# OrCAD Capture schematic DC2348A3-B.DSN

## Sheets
1 PAGE2: size B; title: HIGH POWER POLY-PHASE; rev: 3; company: TM; note: BI-DIRECTIONAL SUPPLY/CHARGER
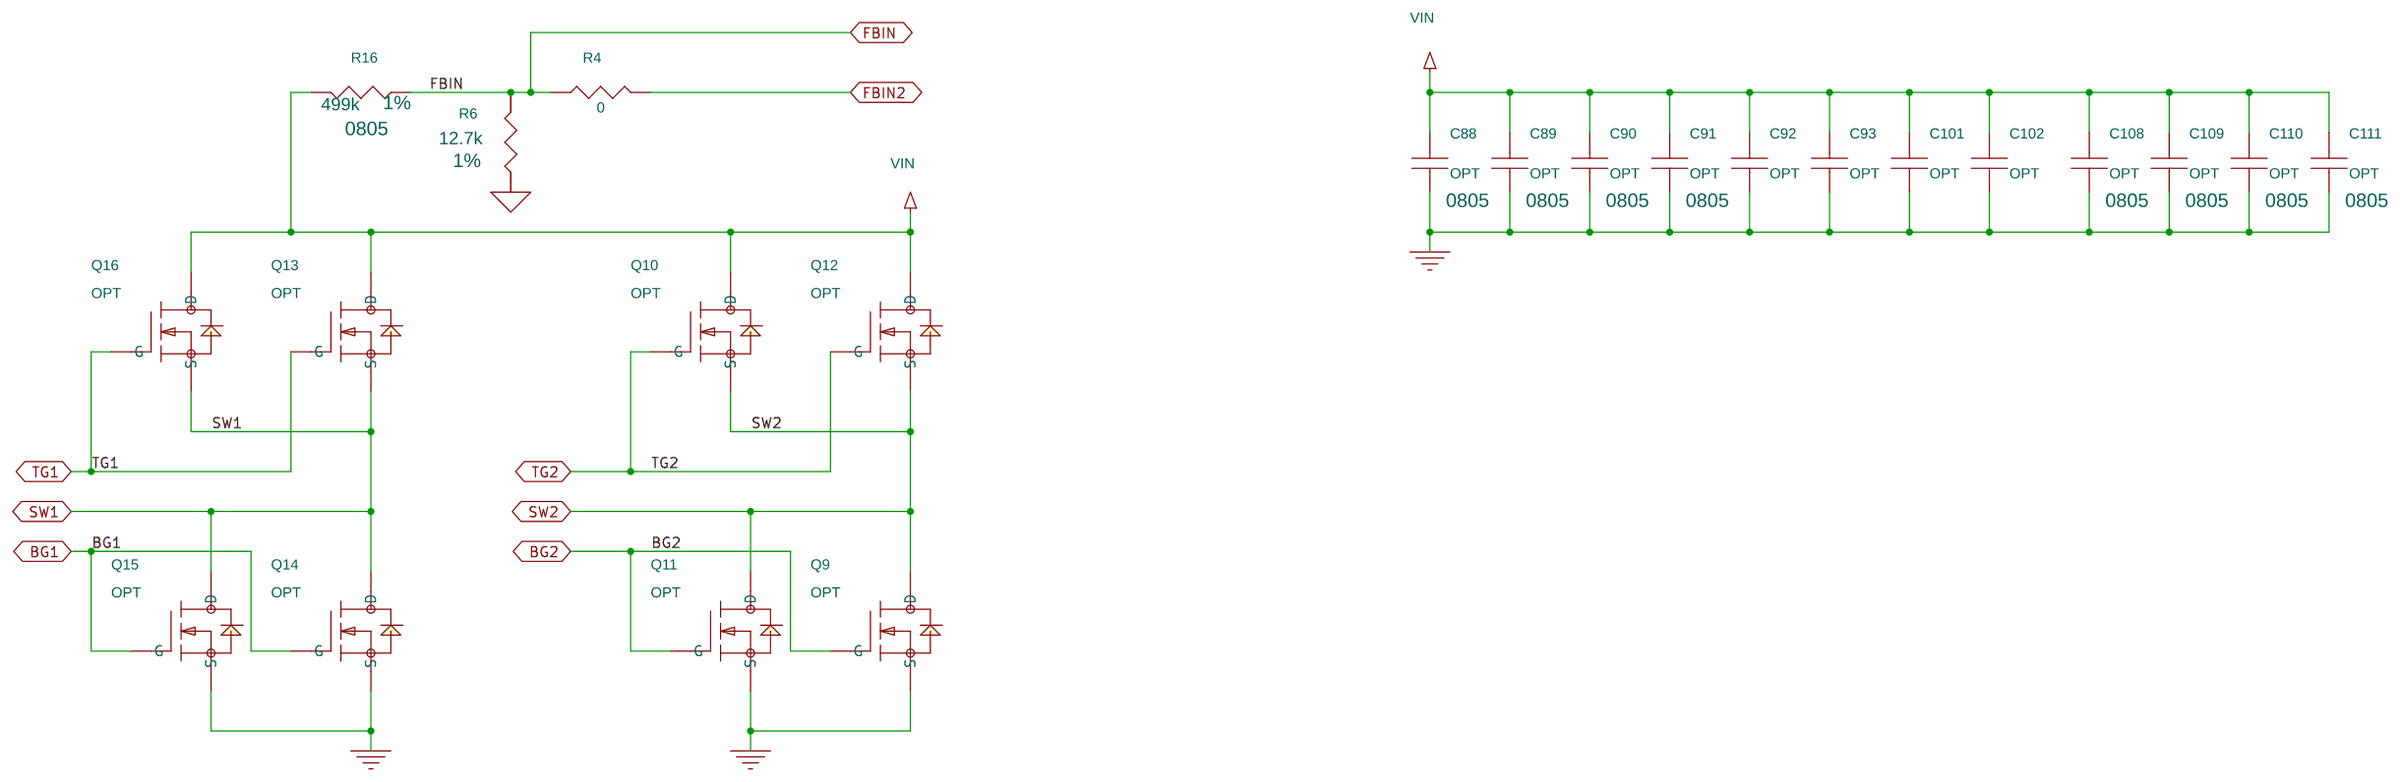
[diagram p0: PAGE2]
2 PAGE1: size Custom
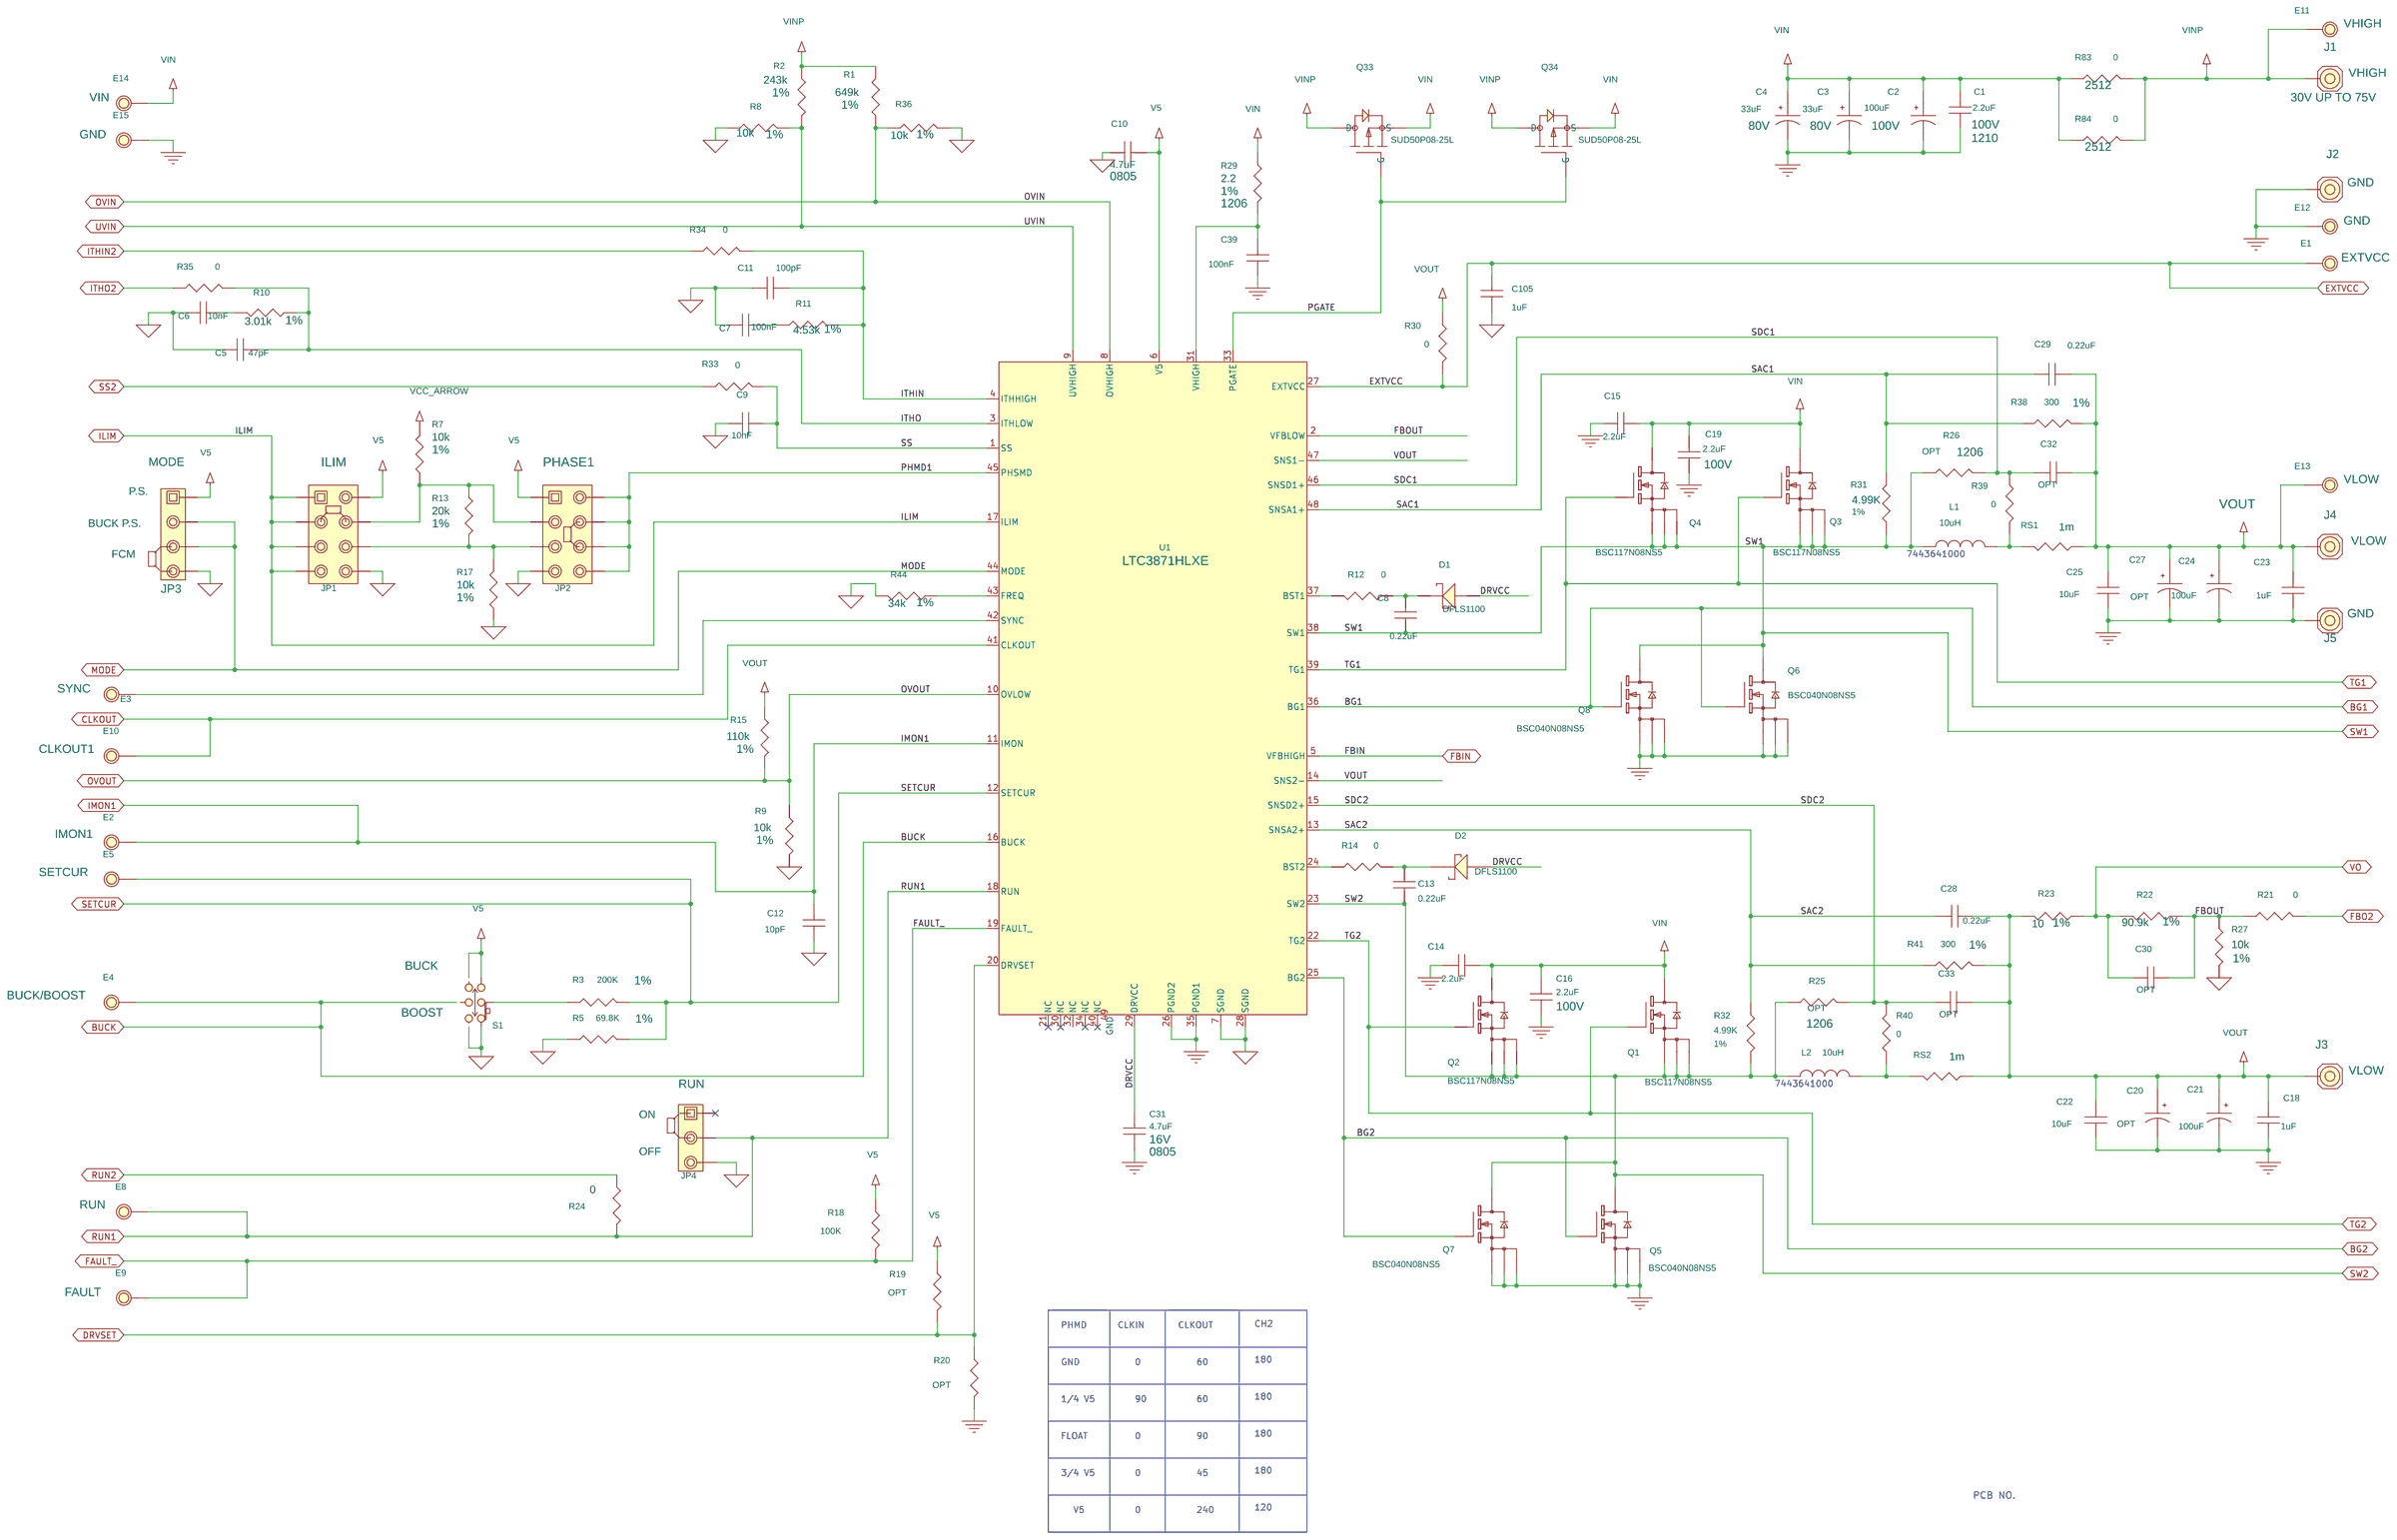
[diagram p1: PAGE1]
3 PAGE3: size A
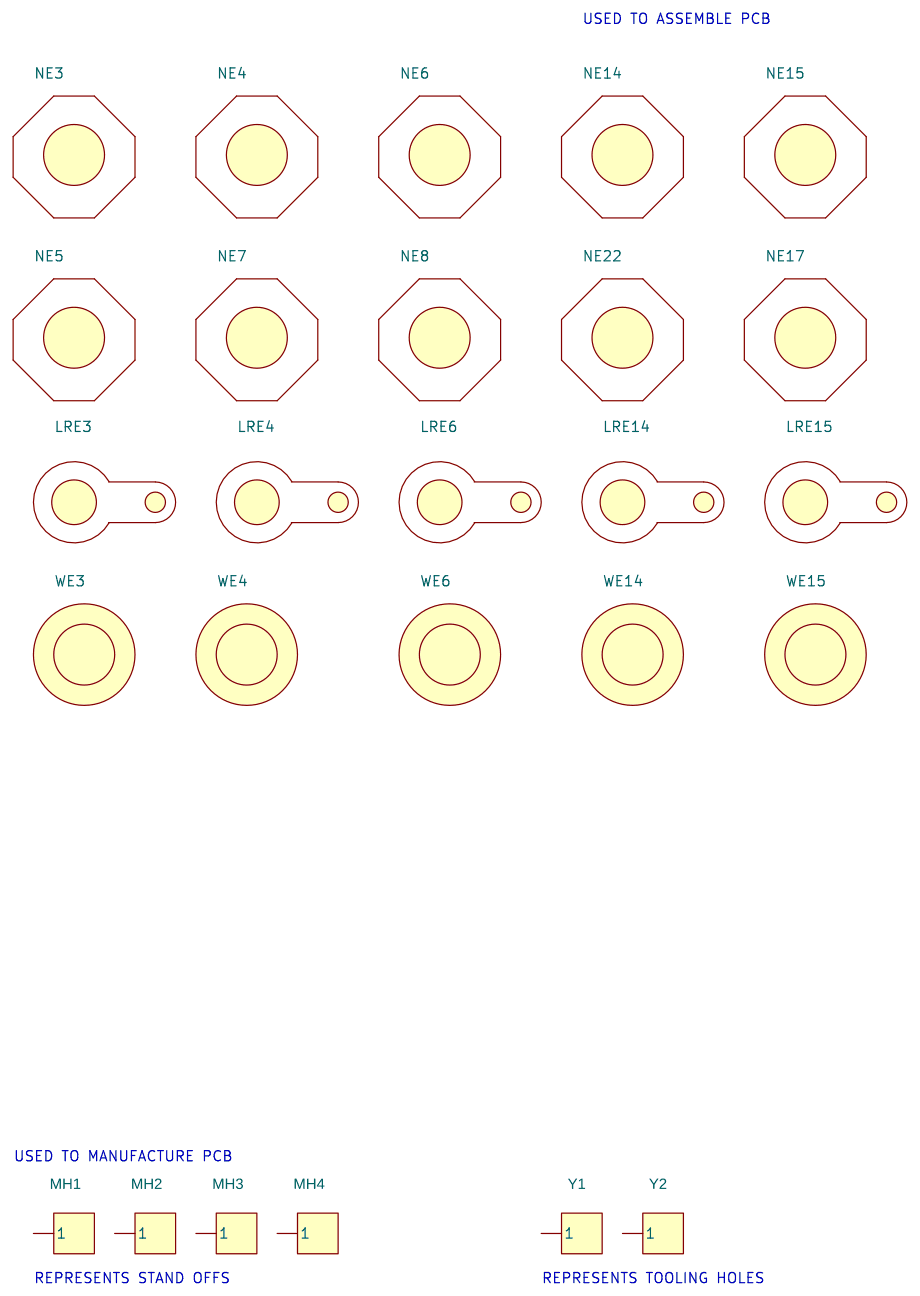
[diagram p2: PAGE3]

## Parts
sheet PAGE1
C1  2.2uF  [1210]
C2  100uF  [CAP\SANYO\CE_16X16.5]
C3  33uF  [CAP\SANYO\8X10.2\CE]
C4  33uF  [CAP\SANYO\8X10.2\CE]
C5  47pF  [0603]
C6  10nF  [0603]
C7  100nF  [0603]
C8  0.22uF  [0603]
C9  10nF  [0603]
C10  4.7uF  [0805]
C11  100pF  [0603]
C12  10pF  [0603]
C13  0.22uF  [0603]
C14  2.2uF  [1210]
C15  2.2uF  [1210]
C16  2.2uF  [1210]
C18  1uF  [0603]
C19  2.2uF  [1210]
C20  OPT  [CAP\SANYO\SVPA_E7]
C21  100uF  [CAP\PANASONIC\6.3X7.7\ZA]
C22  10uF  [1206]
C23  1uF  [0603]
C24  100uF  [CAP\PANASONIC\6.3X7.7\ZA]
C25  10uF  [1206]
C27  OPT  [CAP\SANYO\SVPA_E7]
C28  0.22uF  [0603]
C29  0.22uF  [0603]
C30  OPT  [0603]
C31  4.7uF  [0805]
C32  OPT  [0603]
C33  OPT  [0603]
C39  100nF  [0603]
C105  1uF  [0603]
D1  DFLS1100  [POWERDI_123]
D2  DFLS1100  [POWERDI_123]
E1  EXTVCC  [MM/2501]
E2  IMON1  [MM/2501]
E3  SYNC  [MM/2501]
E4  BUCK/BOOST  [MM/2501]
E5  SETCUR  [MM/2501]
E8  RUN  [MM/2501]
E9  FAULT  [MM/2501]
E10  CLKOUT1  [MM/2501]
E11  VHIGH  [MM/2501]
E12  GND  [MM/2501]
E13  VLOW  [MM/2501]
E14  VIN  [MM/2501]
E15  GND  [MM/2501]
J1  Testpin  [con\lug\10]
J2  Testpin  [con\lug\10]
J3  Testpin  [con\lug\10]
J4  Testpin  [con\lug\10]
J5  Testpin  [con\lug\10]
JP1  2 Pins 2mm Ctrs.  [HDR2X4_2MM]
JP2  2 Pins 2mm Ctrs.  [HDR2X4_2MM]
JP3  3 Pins 2mm Ctrs.  [HDR_1X4_2MM]
JP4  3 Pins 2mm Ctrs.  [commcon2802s03g2]
L1  10uH  [IND\CLCRFT\SER2900]
L2  10uH  [IND\CLCRFT\SER2900]
Q1  BSC117N08NS5  [LFPAK]
Q2  BSC117N08NS5  [LFPAK]
Q3  BSC117N08NS5  [LFPAK]
Q4  BSC117N08NS5  [LFPAK]
Q5  BSC040N08NS5  [LFPAK]
Q6  BSC040N08NS5  [LFPAK]
Q7  BSC040N08NS5  [LFPAK]
Q8  BSC040N08NS5  [LFPAK]
Q33  SUD50P08-25L  [TO252-3]
Q34  SUD50P08-25L  [TO252-3]
R1  649k  [0603]
R2  243k  [0603]
R3  200K  [0603]
R5  69.8K  [0603]
R7  10k  [0603]
R8  10k  [0603]
R9  10k  [0603]
R10  3.01k  [0603]
R11  4.53k  [0603]
R12  0  [0603]
R13  20k  [0603]
R14  0  [0603]
R15  110k  [0603]
R17  10k  [0603]
R18  100K  [0603]
R19  OPT  [0603]
R20  OPT  [0603]
R21  0  [0603]
R22  90.9k  [0603]
R23  10  [0603]
R24  0  [0603]
R25  OPT  [1206]
R26  OPT  [1206]
R27  10k  [0603]
R29  2.2  [1206]
R30  0  [0603]
R31  4.99K  [0603]
R32  4.99K  [0603]
R33  0  [0603]
R34  0  [0603]
R35  0  [0603]
R36  10k  [0603]
R38  300  [0603]
R39  0  [0603]
R40  0  [0603]
R41  300  [0603]
R44  34k  [0603]
R83  0  [2512]
R84  0  [2512]
RS1  1m  [2010]
RS2  1m  [2010]
S1  JP3X1/079\NO\12  [JS202011]
U1  LTC3871HLXE  [LT_LXE-LQFP_7X7]
XJP1  2mm Ctrs.
XJP4  2mm Ctrs.
XJP6  2mm Ctrs.
XJP7  2mm Ctrs.
sheet PAGE2
C88  OPT  [0805]
C89  OPT  [0805]
C90  OPT  [0805]
C91  OPT  [0805]
C92  OPT  [0603]
C93  OPT  [0603]
C101  OPT  [0603]
C102  OPT  [0603]
C108  OPT  [0805]
C109  OPT  [0805]
C110  OPT  [0805]
C111  OPT  [0805]
Q9  OPT  [TO252-3]
Q10  OPT  [TO252-3]
Q11  OPT  [TO252-3]
Q12  OPT  [TO252-3]
Q13  OPT  [TO252-3]
Q14  OPT  [TO252-3]
Q15  OPT  [TO252-3]
Q16  OPT  [TO252-3]
R4  0  [0603]
R6  12.7k  [0603]
R16  499k  [0805]
sheet PAGE3
LRE3  Lug_Ring
LRE4  Lug_Ring
LRE6  Lug_Ring
LRE14  Lug_Ring
LRE15  Lug_Ring
MH1  CON1  [KEYSTONE_8831]
MH2  CON1  [KEYSTONE_8831]
MH3  CON1  [KEYSTONE_8831]
MH4  CON1  [KEYSTONE_8831]
NE3  NUT
NE4  NUT
NE5  NUT
NE6  NUT
NE7  NUT
NE8  NUT
NE14  NUT
NE15  NUT
NE17  NUT
NE22  NUT
WE3  Washer
WE4  Washer
WE6  Washer
WE14  Washer
WE15  Washer
Y1  CON1  [TOOL\ALGNHL\70]
Y2  CON1  [TOOL\ALGNHL\70]

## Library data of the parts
C1 C14-C16 C19 = CAP_NP_0: CAP, 1210 2.2uF 10% 100V X7R; Part Number: AVX 12101C225KAT2A; VOLTAGE: 100V
C2 = CAP_POL: CAP, 100uF 20% 100V ELEC; Part Number: SUN ELECT. 100CE100KXT; VOLTAGE: 100V
C3 C4 = CAP_POL: CAP, 33uF 20% 80V ELEC; MANUFACTURING: 10TPE330M; Part Number: PANASONIC EEE-FK1K330P; VOLTAGE: 80V
C5 = CAP_NP_0: CAP, 0603 47pF 10% 50V C0G; 1PART: 16V; Part Number: AVX 06035A470KAT2A; VOLTAGE: 50V
C6 = CAP_NP_0: CAP, 0603 10nF 10% 100V X7R; Part Number: AVX 06035C104KAT2A; VOLTAGE: 50V
C7 C39 = CAP_NP_0: CAP, 0603 100nF 10% 50V X7R; Part Number: AVX 06035C104KAT2A; VOLTAGE: 50V
C8 C13 = CAP_NP_0: CAP, 0603 0.22uF 10% 25V X5R; Part Number: AVX 06033D224KAT2A; VOLTAGE: 25V
C9 = CAP_NP_0: CAP, 0603 10nF 10% 100V X7R; 1PART: 16V; Part Number: AVX 06035C104KAT2A; VOLTAGE: 25V
C10 = CAP_NP_0: CAP, 0805 4.7uF 10% 16V X7R; Part Number: AVX 0805YC475KAT2A; VOLTAGE: 16V
C11 = CAP_NP_0: CAP, 0603 100pF 10% 100V NPO; Part Number: AVX 06031A101KAT2A; VOLTAGE: 100V
C12 = CAP_NP_0: CAP, 0603 10pF 10% 100V C0G; Part Number: AVX 06031A100KAT2A / AVX; VOLTAGE: 100V
C18 C23 C105 = CAP_NP_0: CAP, 0603 1uF 10% 25V X7R; Part Number: MURATA GRM188R71E105KA12D; VOLTAGE: 16V
C20 C27 = CAP_POL: CAP, ALUM OPTION; MANUFACTURING: 10TPE330M; Part Number: OPTION; VOLTAGE: 16V
C21 = CAP_POL: CAP, 100uF 20% 25V ALUM; Part Number: PANASONIC EEHZA1E101XP; VOLTAGE: 25V
C22 C25 = CAP_NP_0: CAP, 1206 10uF 10% 25V X7R; Part Number: MURATA GRM31CR71E106KA12L; VOLTAGE: 16V
C24 = CAP_POL: CAP, 100uF 20% 25V ALUM; MANUFACTURING: 10TPE330M; Part Number: PANASONIC EEHZA1E101XP; VOLTAGE: 25V
C28 C29 = CAP_NP_0: CAP, 0603 0.22uF 10% 25V X5R; Part Number: AVX 06033D224KAT2A; VOLTAGE: 16V
C30 = CAP_NP_0: CAP, 0603 OPTION; Part Number: OPTION; VOLTAGE: ( Opt. )
C31 = CAP_NP_0: CAP, 0805 4.7uF 10% 16V X7R; 1PART: 16V; Part Number: AVX 0805YC475KAT2A; VOLTAGE: 16V
C32 C33 = CAP_NP_0: CAP, 0603 OPTION; Part Number: OPTION
D1 D2 = D-SCHOTTKY_0: DIODE, SCHOTTKY, RECTIFIER; Field1: SOD323; Part Number: DIODES INC. DFLS1100-7
E1-E5 E8-E15 = MillMax-2501: TURRET; Part Number: MIIL-MAX 2501-2-00-80-00-00-07-0
J1 = PEM-kfh-032-10: STUD, TESTPIN; 10th Part Field: 30V UP TO 75V; 9th Part Field: VHIGH; Part Number: PEM KFH-032-10
J2 J5 = PEM-kfh-032-10: STUD, TESTPIN; 10th Part Field: 5 - 24V #; 9th Part Field: GND; Part Number: PEM KFH-032-10
J3 J4 = PEM-kfh-032-10: STUD, TESTPIN; 10th Part Field: 12V / 50A; 9th Part Field: VLOW; Part Number: PEM KFH-032-10
JP1 = Samtec_TMM-_0: HEADER, 4PIN, DBL ROW 2mm; 10th Part Field: ILIM; 4th Part Field: BURST; 5th Part Field: FCC; 7th Part Field: SYNC; 9th Part Field: ILIM; Part Number: WURTH ELEKTRONIK 62000821121
JP2 = Samtec_TMM-_0: HEADER, 4PIN, DBL ROW 2mm; 4th Part Field: BURST; 5th Part Field: FCC; 7th Part Field: SYNC; 9th Part Field: PHASE1; Part Number: WURTH ELEKTRONIK 62000821121
JP3 = Samtec_TMM-103-02-L-S_0: HEADER, 4PIN, 2mm; 11th Part Field: BUCK P.S.; 12th Part Field: MODE; 4th Part Field: P.S.; 5th Part Field: ?; 9th Part Field: FCM; Part Number: WURTH ELEKTRONIK 62000411121
JP4 = Samtec_TMM-103-02-L-S: HEADER, 2mm, 3PIN; 11th Part Field: OFF; 12th Part Field: RUN; 9th Part Field: ON; Part Number: WURTH ELEKTRONIK 62000311121
L1 = INDUCTOR: IND, 10uH; Part Number: WURTH 7443641000 / COILCRAFT SER2918H-103; manufacturing: Coilcraft SER1360-802KL
L2 = INDUCTOR: IND, 10uH; Part Number: WURTH 7443641000 / COILCRAFT SER2918H-103; manufacturing: Coilcraft SER1360-472KL
Q1-Q4 = 2N7002_28: XSTR,  MOSFET N-CH 80V 100A TDSON-8; Part Number: INFINEON BSC117N08NS5
Q5-Q8 = 2N7002_28: XSTR,  MOSFET N-CH 80V 100A TDSON-8; Part Number: INFINEON BSC040N08NS5
Q33 Q34 = Si2311DS_0: XSTR, SIPMOS, P-CHANNEL; Part Number: VISHAY SUD50P08-25L
R1 = R_1: RES, 0603 649k OHMS 1% 1/10W; %: 1%; Part Number: VISHAY CRCW0603649KFKEA
R2 = R_1: RES, 0603 243k OHMS 1% 1/10W; %: 1%; Part Number: VISHAY CRCW0603243KFKEA
R3 = R_1: RES, 0603 200k OHMS 1% 0.1W; %: 1%; Part Number: VISHAY CRCW0603200KFKEA
R5 = R_1: RES, 0603 69.8k OHMS 1% 0.1W; %: 1%; Part Number: VISHAY CRCW060369K8FKEA
R7-R9 R17 R27 R36 = R_1: RES, 0603 10k OHMS 1% 1/10W; %: 1%; Part Number: VISHAY CRCW060310K0FKEA
R10 = R_1: RES, 0603 3.01k OHMS 1% 1/10W; %: 1%; Part Number: VISHAY CRCW06033K01FKEA
R11 = R_1: RES, 0603 4.53k OHMS 1% 1/10W; %: 1%; Part Number: VISHAY CRCW06034K53FKEA
R12 R14 = R_1: RES, 0603 0 OHM JUMPER; %: 1%; Part Number: VISHAY CRCW06030000Z0EA
R13 = R_1: RES, 0603 20k OHMS 1% 1/10W; %: 1%; Part Number: VISHAY CRCW060320K0FKEA
R15 = R_1: RES, 0603 110k OHMS 1% 1/10W; %: 1%; Part Number: VISHAY CRCW0603110KFKEA
R18 = R_1: RES, 0603 100k OHMS 5% 1/10W; %: 1%; Part Number: VISHAY CRCW0603100KJNEA
R19 = R_1: RES, 0603 OPTION; %: 1%; Part Number: OPTION
R20 = R_1: RES, 0603 OPTION; %: 0.1%; Part Number: OPTION
R4 R21 R24 R30 R33-R35 R39 R40 = R_1: RES, 0603 0 OHM JUMPER; %: 0.1%; Part Number: VISHAY CRCW06030000Z0EA
R22 = R_1: RES, 0603 90.9k OHMS 1% 1/10W; %: 1%; Part Number: VISHAY CRCW060390K9FKEA
R23 = R_1: RES, 0603 10 OHMS 1% 1/10W; %: 1%; Part Number: VISHAY CRCW060310R0FKEA
R25 R26 = R_1: RES, 1206 OPTION; %: 0.1%; Part Number: OPTION
R29 = R_1: RES. 1206 2.2 OHMS 1% 1/4W; %: 1%; Part Number: VISHAY CRCW12062R20FKEA
R31 R32 = R_1: RES, 0603 4.99K OHMS 1% 0.1W; %: 1%; Part Number: VISHAY CRCW06034K99FKEA
R38 R41 = R_1: RES, 0603 300 OHMS 1% 0.1W; %: 1%; Part Number: VISHAY CRCW0603300RFKEA
R44 = R_1: RES, 0603 34k OHMS 1% 0.1W; %: 1%; Part Number: VISHAY CRCW060334K0FKEA
R83 R84 = R_1: RES, 2512 0 OHM JUMPER; %: 0.1%; Part Number: VISHAY CRCW25120000Z0EG
RS1 RS2 = R_1: RES, 2010 0.001 OHM 1% 1W; %: 0.1%; Part Number: VISHAY WSL20101L000FEA18
S1 = JP3X1_079_NO_12_3: SWITCH, SUBMINATURE, SLIDE, SPDT; 1st Part Field: BUCK; 2nd Part Field: BUCK; 3rd Part Field: BOOST; Part Number: C&K-COMPONENTS JS202011CQN
U1 = LTC3890EUFD_78: IC, HIGH POWER BiDIRECTIONAL SUPPLY; Part Number: LINEAR TECH. LTC3871HLXE#PBF
XJP1 XJP7 = Samtec_2SN-BK-G_0: SHUNT, 2mm; Part Number: WURTH ELEKTRONIK 60800213421
XJP4 XJP6 = Samtec_2SN-BK-G: SHUNT, 2mm; Part Number: WURTH ELEKTRONIK 60800213421
C88-C91 C108-C111 = CAP_NP_0: CAP, 0805 OPTION; Part Number: OPTION; VOLTAGE: 50V
C92 C93 C101 C102 = CAP_NP_0: CAP, 0603 OPTION; Part Number: OPTION; VOLTAGE: 50V
Q9-Q16 = MOSFET_N-CHANNEL_0: XSTR, MOSFET OPTION; Part Number: INFINEON IPD60N10S4-12 OPTION
R6 = R_1: RES, 0603 12.7k OHMS 1% 1/10W; %: 1%; Part Number: VISHAY CRCW060312K7FKEA
R16 = R_1: RES, 0805 499k OHMS 1% 1/8W; %: 1%; Part Number: VISHAY CRCW0805499KFKEA
LRE3 LRE4 LRE6 LRE14 LRE15 = Lug_Ring: LUG RING, #10; Part Number: KEYSTONE 8205
MH1-MH4 = CON1: STANDOFF, SNAP ON; Part Number: KEYSTONE 8834
NE3-NE8 NE14 NE15 NE17 NE22 = NUT: NUT, BRASS 10-32; Part Number: ANY #10-32
WE3 WE4 WE6 WE14 WE15 = Washer: WASHER, #10 TIN PLATED BRASS; Part Number: ANY #10 EXT BZ TN
Y1 Y2 = CON1: DO NOT STUFF; Part Number: PADS ONLY

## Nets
GND: C1.1 C2.2 C3.2 C4.2 C14.2 C15.1 C16.1 C18.1 C19.1 C20.2 C21.2 C22.1 C23.1 C24.2 C25.1 C27.2 C31.2 C39.1 C88.1 C89.1 C90.1 C91.1 C92.1 C93.1 C101.1 C102.1 C108.1 C109.1 C110.1 C111.1 E12.1 E15.1 J2.1 J5.1 Q5.1 Q5.2 Q5.3 Q6.1 Q6.2 Q6.3 Q7.1 Q7.2 Q7.3 Q8.1 Q8.2 Q8.3 Q9.3(S) Q11.3(S) Q14.3(S) Q15.3(S) R20.1 U1.26(PGND2) U1.35(PGND1) U1.49(GND)
GNDSIGNAL: C5.1 C6.1 C7.1 C9.1 C10.1 C11.1 C12.1 C105.2 JP1.8 JP2.7 JP3.4 JP4.3 R5.1 R6.1 R8.1 R9.1 R17.1 R27.1 R36.1 R44.2 S1.3 S1.6 U1.7(SGND) U1.28(SGND)
V5: C10.2 JP1.2 JP2.1 JP3.1 R7.2 R18.2 R19.2 S1.1 S1.4 U1.6(V5)
VIN: C1.2 C2.1 C3.1 C4.1 C14.1 C15.2 C16.2 C19.2 C88.2 C89.2 C90.2 C91.2 C92.2 C93.2 C101.2 C102.2 C108.2 C109.2 C110.2 C111.2 E14.1 Q1.5 Q2.5 Q3.5 Q4.5 Q10.2(D) Q12.2(D) Q13.2(D) Q16.2(D) Q33.3(S) Q34.3(S) R16.2 R29.2 R83.1 R84.1
VINP: E11.1 J1.1 Q33.2(D) Q34.2(D) R1.1 R2.2 R83.2 R84.2
BG1: Q6.4 Q8.4 Q14.1(G) Q15.1(G) U1.36(BG1)
BG2: Q5.4 Q7.4 Q9.1(G) Q11.1(G) U1.25(BG2)
BUCK: E4.1 S1.5 U1.16(BUCK)
CLKOUT: E10.1 U1.41(CLKOUT)
DRVCC: C31.1 D1.2 D2.2 U1.29(DRVCC)
DRVSET: R19.1 R20.2 U1.20(DRVSET)
EXTVCC: C105.1 E1.1 R30.1 U1.27(EXTVCC)
FAULT_: E9.1 R18.1 U1.19(FAULT_)
FBIN: R4.2 R6.2 R16.1 U1.5(VFBHIGH)
FBIN2: R4.1
FBO2: R21.1
FBOUT: C30.2 R21.2 R22.1 R27.2 U1.2(VFBLOW)
ILIM: JP1.1 JP1.3 JP1.5 JP1.7 U1.17(ILIM)
IMON1: C12.2 E2.1 U1.11(IMON)
ITHIN: C11.2 R11.1 R34.2 U1.4(ITHHIGH)
ITHIN2: R34.1
ITHO: C5.2 R10.1 R35.2 U1.3(ITHLOW)
ITHO2: R35.1
MODE: JP3.2 JP3.3 U1.44(MODE)
OVIN: R1.2 R36.2 U1.8(OVHIGH)
OVOUT: R9.2 R15.1 U1.10(OVLOW)
PGATE: Q33.1(G) Q34.1(G) U1.33(PGATE)
PHMD1: JP2.2 JP2.4 JP2.6 JP2.8 U1.45(PHSMD)
RUN1: E8.1 JP4.2 R24.1 U1.18(RUN)
RUN2: R24.2
SAC1: C29.1 R31.2 R38.2 U1.48(SNSA1+)
SAC2: C28.2 R32.1 R41.1 U1.13(SNSA2+)
SDC1: C32.2 R26.1 R39.2 U1.46(SNSD1+)
SDC2: C33.1 R25.2 R40.2 U1.15(SNSD2+)
SETCUR: E5.1 R3.2 R5.2 U1.12(SETCUR)
SS: C9.2 R33.2 U1.1(SS)
SS2: R33.1
SW1: C8.1 L1.1 Q3.1 Q3.2 Q3.3 Q4.1 Q4.2 Q4.3 Q6.5 Q8.5 Q13.3(S) Q14.2(D) Q15.2(D) Q16.3(S) R26.2 R31.1 U1.38(SW1)
SW2: C13.2 L2.2 Q1.1 Q1.2 Q1.3 Q2.1 Q2.2 Q2.3 Q5.5 Q7.5 Q9.2(D) Q10.3(S) Q11.2(D) Q12.3(S) R25.1 R32.2 U1.23(SW2)
TG1: Q3.4 Q4.4 Q13.1(G) Q16.1(G) U1.39(TG1)
TG2: Q1.4 Q2.4 Q10.1(G) Q12.1(G) U1.22(TG2)
UVIN: R2.1 R8.2 U1.9(UVHIGH)
VO: C30.1 R22.2 R23.1
VOUT: C18.2 C20.1 C21.1 C22.2 C23.2 C24.1 C25.2 C27.1 C28.1 C29.2 C32.1 C33.2 E13.1 J3.1 J4.1 R15.2 R23.2 R30.2 R38.1 R41.2 RS1.1 RS2.2 U1.14(SNS2-) U1.47(SNS1-)
N16723613: C39.2 R29.1 U1.31(VHIGH)
N17352805: L1.2 R39.1 RS1.2
N19612564: L2.1 R40.1 RS2.1
N19638427: C7.2 R11.2
N19643876: C6.2 R10.2
N19689499: JP1.6 JP2.5 R13.1 R17.2
N19693977: JP1.4 JP2.3 R7.1 R13.2
N19716351: R44.1 U1.43(FREQ)
N19723679: E3.1 U1.42(SYNC)
N21972963: R14.1 U1.24(BST2)
N22013700: C8.2 D1.1 R12.2
N22013776: R12.1 U1.37(BST1)
N22019659: C13.1 D2.1 R14.2
N22085902: R3.1 S1.2

Not connected (* = marked no-connect by the designer): JP4 1*; MH1 1; MH2 1; MH3 1; MH4 1; U1 21(NC)* 30(NC)* 32(NC) 34(NC)* 40(NC)*; Y1 1; Y2 1

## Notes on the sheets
sheet 2
- 7443641000
- 7443641000
- PHMD
- CLKIN
- CLKOUT
- CH2
- GND
- 0
- 60
- 180
- 1/4 V5
- 90
- 60
- 180
- FLOAT
- 0
- 90
- 180
- 3/4 V5
- 0
- 45
- 180
- PCB NO.
- V5
- 0
- 240
- 120
sheet 3
- USED TO ASSEMBLE PCB
- USED TO MANUFACTURE PCB
- REPRESENTS STAND OFFS
- REPRESENTS TOOLING HOLES
